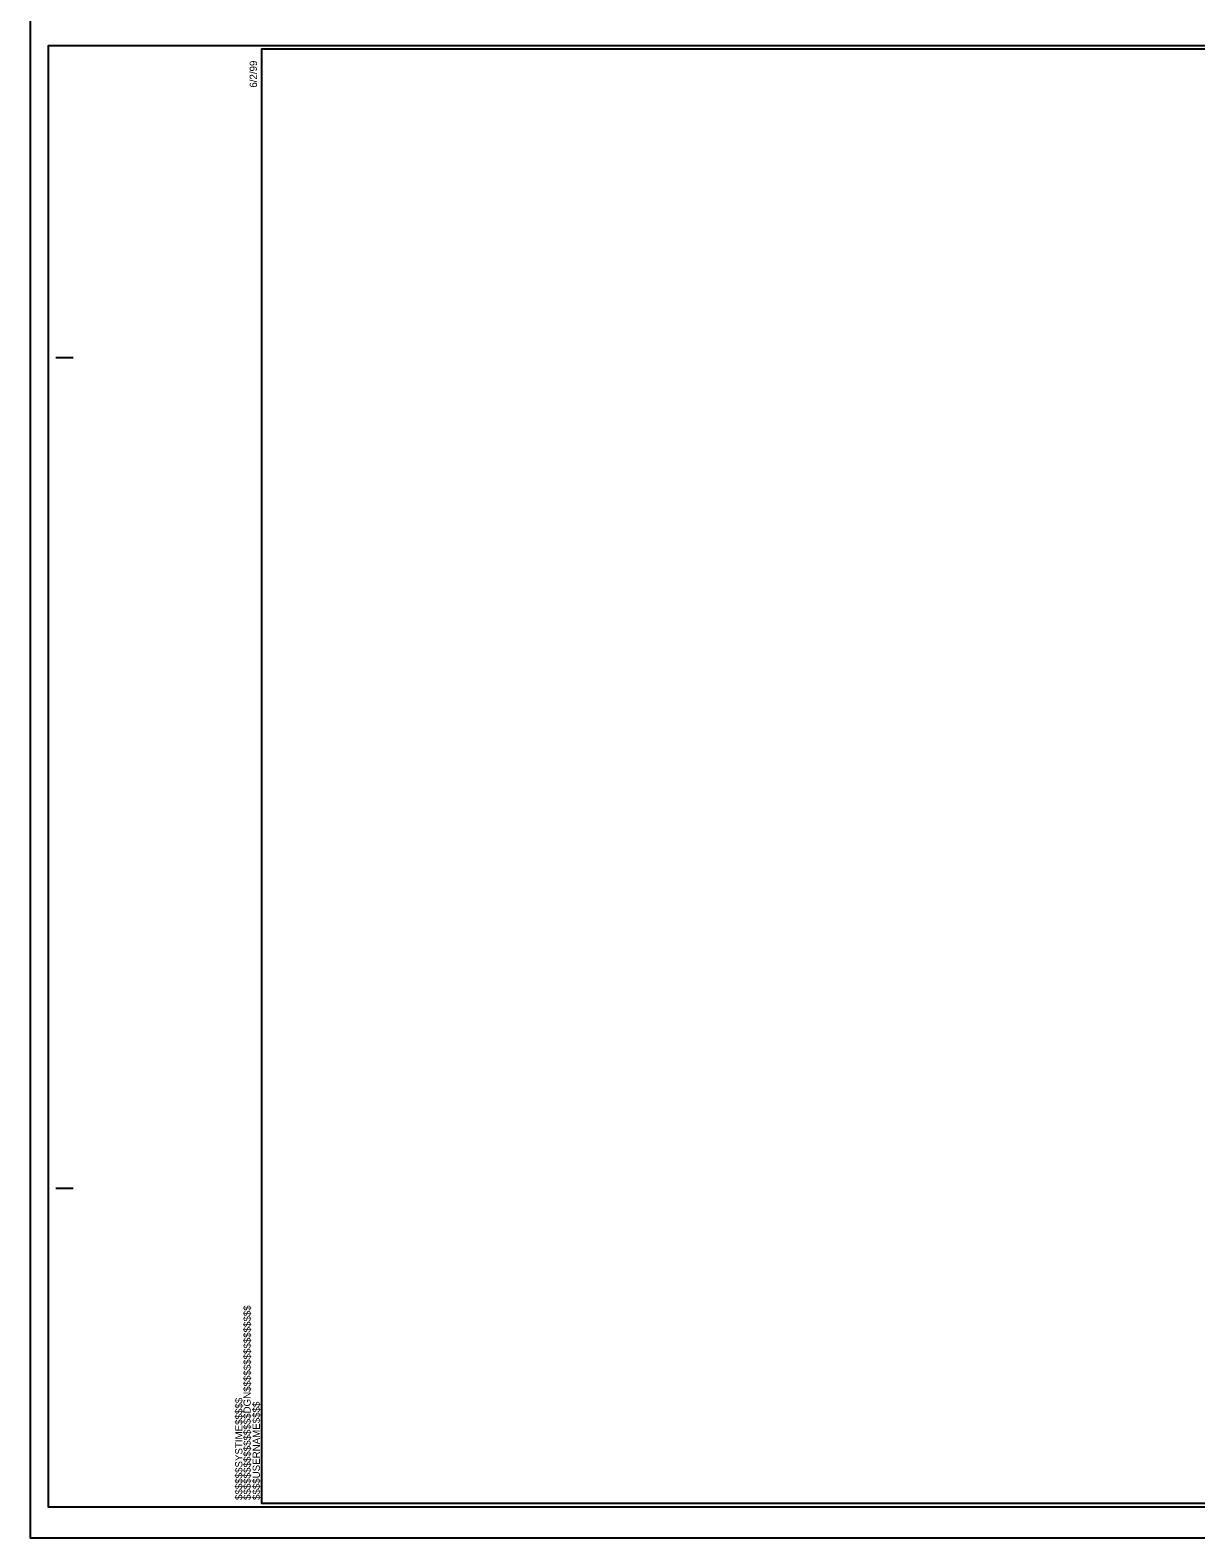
# Model space of a CAD drawing. Extents: x 1664524 to 1666208, y 587901 to 592296.
# Drawn here: x 1664524 to 1665366, y 587901 to 588990 of the extents above; entities that cross this region are included whole.
import ezdxf

# ---------------------------------------------------------------- set-up
doc = ezdxf.new("R2010")
doc.units = 0
for name, color, linetype in [('Prop Horizontal Alignment Tick Large', 7, 'Continuous'), ('Prop Horizontal Alignment Tick Small', 7, 'Continuous'), ('Sheet Cutting Line CELL', 7, 'Continuous'), ('Sheet Typical CELL', 7, 'Continuous')]:
    doc.layers.add(name, color=color, linetype=linetype)

msp = doc.modelspace()

# ---------------------------------------------------------------- linework, layer by layer
at = {"layer": 'Prop Horizontal Alignment Tick Large'}
msp.add_lwpolyline([(1666203.3, 588978.9), (1664536.8, 588978.9), (1664536.8, 587923.8), (1666203.3, 587923.8)], close=True, dxfattribs=at)
at = {"layer": 'Prop Horizontal Alignment Tick Small'}
msp.add_lwpolyline([(1666207.8, 589001.3), (1664523.8, 589001.3), (1664523.8, 587901.3), (1666207.8, 587901.3)], close=True, dxfattribs=at)
at = {"layer": 'Sheet Cutting Line CELL'}
for p, q in [((1664523.8, 589001.3), (1664523.8, 587901.3)), ((1664523.8, 587901.3), (1666207.8, 587901.3))]:
    msp.add_line(p, q, dxfattribs=at)
at = {"layer": 'Sheet Typical CELL'}
for p, q in [((1664542.3, 588753.8), (1664554.8, 588753.8)), ((1664542.3, 588153.8), (1664554.8, 588153.8)), ((1664690.8, 587926.3), (1664690.8, 587926.3)), ((1664690.8, 587926.3), (1664690.8, 587926.3)), ((1664690.8, 587926.3), (1664690.8, 587926.3)), ((1664690.8, 587926.3), (1664690.8, 587926.3)), ((1664690.8, 587926.3), (1664690.8, 587926.3)), ((1664690.8, 587926.3), (1664690.8, 587926.3))]:
    msp.add_line(p, q, dxfattribs=at)
msp.add_lwpolyline([(1666190.8, 588976.3), (1664690.8, 588976.3), (1664690.8, 587926.3), (1666190.8, 587926.3)], close=True, dxfattribs=at)
msp.add_lwpolyline([(1664728.3, 587926.3), (1664728.3, 587926.3)], dxfattribs=at)

# ---------------------------------------------------------------- texts
for s, p in [('6/2/99', (1664687.6, 588948.6)), ('$$$$$$$$$$$$$$$$DGN$$$$$$$$$$$$$$$$', (1664683.1, 587928.7)), ('$$$$$$SYSTIME$$$$$', (1664677.1, 587928.7)), ('$$$$USERNAME$$$$', (1664689.7, 587928.7))]:
    msp.add_text(s, height=5.25, rotation=90, dxfattribs=at).set_placement(p)

doc.saveas('drawing.dxf')
